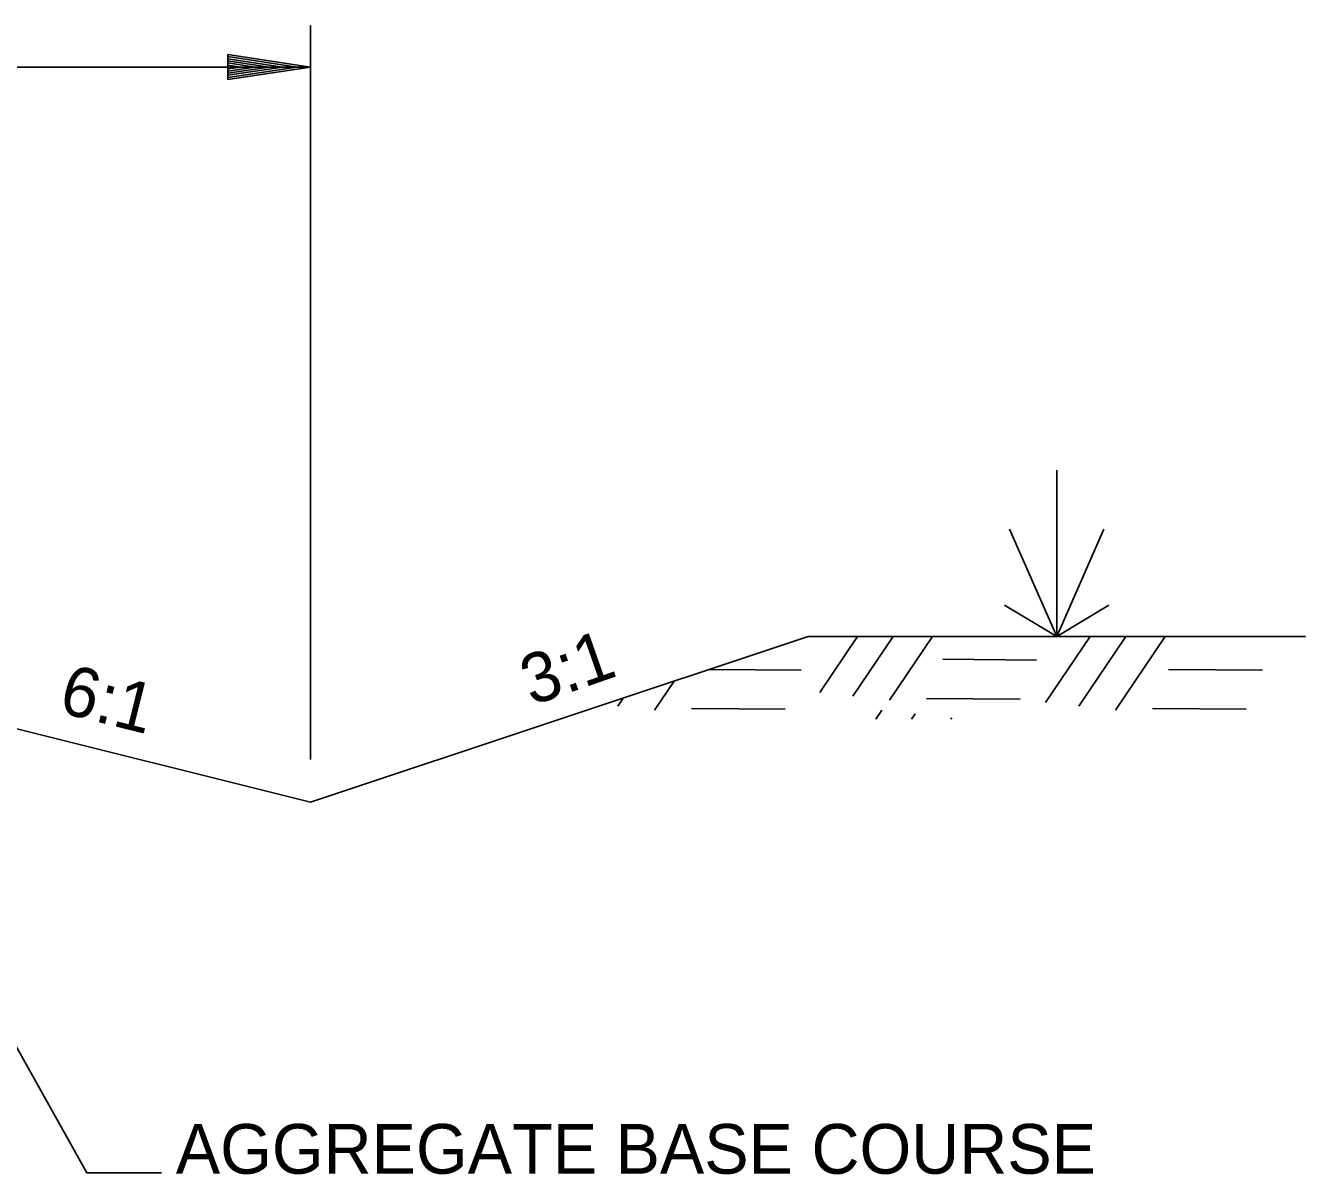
# Model space of a CAD drawing. Extents: x 138 to 3619, y -519 to 1449.
# Drawn here: x 809.3 to 963.7, y 471.7 to 610.4 of the extents above; entities that cross this region are included whole.
import ezdxf

# ---------------------------------------------------------------- set-up
doc = ezdxf.new("R2010")
doc.units = 0
for name, color, linetype in [('R_Annotation', 7, 'Continuous'), ('R_Dimension', 7, 'Continuous'), ('R_Draft', 7, 'Continuous')]:
    doc.layers.add(name, color=color, linetype=linetype)

msp = doc.modelspace()

# ---------------------------------------------------------------- linework, layer by layer
at = {"layer": 'R_Annotation'}
for p, q in [((761.26, 537.26), (843.66, 516.66)), ((843.66, 516.66), (903.66, 536.66)), ((903.66, 536.66), (963.66, 536.66))]:
    msp.add_line(p, q, dxfattribs=at)
at = {"layer": 'R_Dimension'}
for p, q in [((843.66, 521.81), (843.66, 610.39)), ((833.66, 606.89), (843.66, 605.39)), ((833.66, 606.89), (833.66, 603.89)), ((843.66, 605.39), (721.26, 605.39)), ((833.66, 606.64), (841.99, 605.39)), ((833.66, 606.39), (840.27, 605.39)), ((833.66, 606.14), (838.61, 605.39)), ((833.66, 605.88), (836.91, 605.39)), ((833.66, 605.63), (835.24, 605.39)), ((833.66, 603.89), (843.66, 605.39)), ((833.66, 604.9), (836.91, 605.39)), ((833.66, 604.4), (840.27, 605.39)), ((833.66, 604.14), (841.99, 605.39)), ((833.66, 604.65), (838.61, 605.39)), ((833.66, 605.16), (835.24, 605.39)), ((905.08, 529.91), (909.63, 536.66)), ((909.06, 529.45), (913.93, 536.66)), ((913.51, 528.98), (918.69, 536.66)), ((932.33, 528.7), (937.7, 536.66)), ((936.32, 528.24), (942, 536.66)), ((940.77, 527.78), (946.76, 536.66)), ((891.76, 532.69), (902.85, 532.6)), ((919.91, 533.9), (931.22, 533.81)), ((947.16, 532.69), (958.47, 532.6)), ((885.15, 527.78), (887.5, 531.27)), ((880.7, 528.24), (881.36, 529.22)), ((917.96, 529.17), (929.27, 529.08)), ((889.59, 527.96), (900.9, 527.87)), ((911.83, 526.66), (912.58, 527.78)), ((916.13, 526.66), (916.57, 527.31)), ((920.89, 526.66), (921.02, 526.85)), ((945.22, 527.96), (956.52, 527.87))]:
    msp.add_line(p, q, dxfattribs=at)
msp.add_lwpolyline([(825.65, 471.9), (816.66, 471.9), (786, 526.73)], dxfattribs=at)
at = {"layer": 'R_Draft'}
for q in [(933.66, 556.75), (927.97, 549.59), (939.36, 549.59), (927.37, 540.45), (939.96, 540.45)]:
    msp.add_line((933.66, 536.66), q, dxfattribs=at)

# ---------------------------------------------------------------- texts
at = {"layer": 'R_Annotation'}
for s, rotation, p in [('3:1', 19.3394, (870.32, 528.26)), ('6:1', 345.964, (813.08, 527.55))]:
    msp.add_text(s, height=6, rotation=rotation, dxfattribs=at).set_placement(p)
msp.add_text('AGGREGATE BASE COURSE', height=6, dxfattribs=at).set_placement((827.39, 471.81))

doc.saveas('drawing.dxf')
